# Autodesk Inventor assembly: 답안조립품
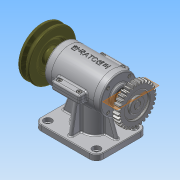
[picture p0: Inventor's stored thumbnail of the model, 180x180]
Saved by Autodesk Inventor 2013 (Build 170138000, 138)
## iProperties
Created: 2015-09
Part Number: 답안조립품
Document SubType Name: Assembly
Designer: Administrator
Mass: 2251.17 g
Surface Area: 1633.51 cm^2
Volume: 528.515 cm^3
Density: 4.25943 g/cm^3
Author: Administrator
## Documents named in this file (17)
- C:\Users\Administrator\Desktop\350908V1025\답안조립품.iam
- C:\Users\Administrator\Desktop\350908V1025\본체.ipt
- C:\Users\Administrator\Desktop\350908V1025\M3x0.5x8.ipt
- C:\Users\Administrator\Desktop\350908V1025\M4x0.5x14.ipt
- C:\Users\Administrator\Desktop\350908V1025\V-벨트풀리.ipt
- C:\Users\Administrator\Desktop\350908V1025\가변스프링.ipt
- C:\Users\Administrator\Desktop\350908V1025\뒤커버.ipt
- C:\Users\Administrator\Desktop\350908V1025\멈춤나사.ipt
- C:\Users\Administrator\Desktop\350908V1025\베어링 6201.ipt
- C:\Users\Administrator\Desktop\350908V1025\베어링 6202.ipt
- C:\Users\Administrator\Desktop\350908V1025\본체 커버.ipt
- C:\Users\Administrator\Desktop\350908V1025\스퍼기어.ipt
- C:\Users\Administrator\Desktop\350908V1025\슬라이드.ipt
- C:\Users\Administrator\Desktop\350908V1025\앞커버.ipt
- C:\Users\Administrator\Desktop\350908V1025\오일실.ipt
- C:\Users\Administrator\Desktop\350908V1025\키4x4.ipt
- C:\Users\Administrator\Desktop\350908V1025\편심축.ipt
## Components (14 placed, 4 different names)
1. M4x0.5x14:1
2. V-벨트풀리:1 — 플러쉬:1, 각도:1
3. 가변스프링:1
4. M4x0.5x14:2
5. M4x0.5x14:3
6. M4x0.5x14:4
7. M3x0.5x8:2
8. M3x0.5x8:6
9. M3x0.5x8:7
10. M3x0.5x8:8
11. M3x0.5x8:1
12. M3x0.5x8:9
13. M3x0.5x8:10
14. M3x0.5x8:11
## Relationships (2: Flush 1, Angle 1)
- 플러쉬:1 [Flush]: V-벨트풀리:1
- 각도:1 [Angle]: V-벨트풀리:1
